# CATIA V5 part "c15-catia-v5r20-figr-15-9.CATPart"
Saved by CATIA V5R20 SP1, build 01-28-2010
Part number: Part1
Bounding box of the stored display mesh (mm): x -50 to 50, y -32.5 to 33.5, z -52 to 1
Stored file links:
  D:\v5_r20\psrt_files_downloaded\c15\c15-catia-v5r20-figr-15-9.CATPart
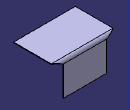
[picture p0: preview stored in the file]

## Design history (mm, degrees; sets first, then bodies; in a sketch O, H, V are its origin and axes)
SheetMetalParameters1: Thickness 1, BendRadius 4, KFactor 0.475772 {= log(min(100,max(20*SheetMetalParameters1.BendRadius,SheetMetalParameters1.Thickness)/SheetMetalParameters1.Thickness))/log(100)/2}, ReliefRadialLength 4, ReliefAxialLength 4, MinimumBendRadius 0
Body1 (main body)
  Sketch1 on xy-plane, origin (0, 0, 0), H (1, 0, 0), V (0, 1, 0)
    line L1 (-50, 32.5) -> (50, 32.5)
    line L2 (50, 32.5) -> (50, -32.5)
    line L3 (50, -32.5) -> (-50, -32.5)
    line L4 (-50, -32.5) -> (-50, 32.5)
    length L1 = 100
    length L2 = 65
    horizontal: L1 H, L3 H
    vertical: L2 V, L4 V
    symmetry: L4 L2 V, L1 L3 H
  Wall1: Thickness 1, Profile Sketch1
  d_NewWallOnEdge1: NewWallOnEdge_Edge edge [face of Wall1 | face of Wall1], NewWallOnEdge_Length 53, NewWallOnEdge_HeightLimitOffset 0, NewWallOnEdge_WidthOffset1 -15, NewWallOnEdge_WidthOffset2 -15, NewWallOnEdge_Angle 90, NewWallOnEdge_BendRadiusValue 4 {= SheetMetalParameters1.BendRadius}, NewWallOnEdge_BendTable SheetMetalParameters1, KFacteur 0.475772 {= log(min(100,max(20*d_NewWallOnEdge1.Radius,SheetMetalParameters1.Thickness)/SheetMetalParameters1.Thickness))/log(100)/2}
